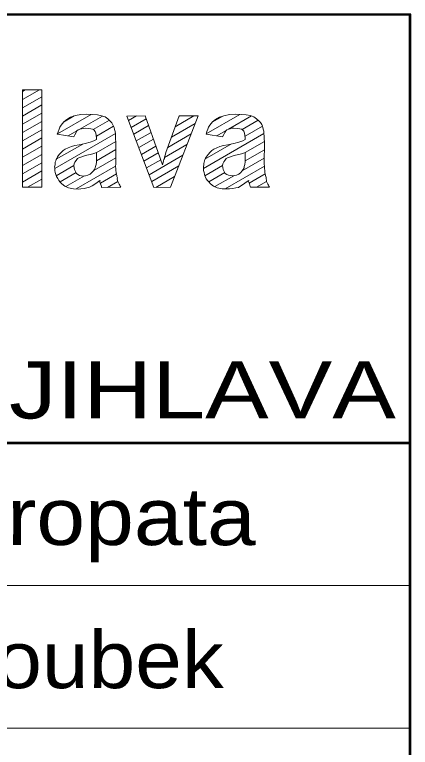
# Model space of a CAD drawing. Extents: x -670514 to -669423, y -1130798 to -1130123.
# Drawn here: x -670454.85 to -670449.3, y -1130661.82 to -1130651.55 of the extents above; entities that cross this region are included whole.
import ezdxf
from ezdxf.enums import TextEntityAlignment as Align

# ---------------------------------------------------------------- set-up
doc = ezdxf.new("R2010")
doc.units = 0
doc.header["$LTSCALE"] = 0.24
doc.layers.add('61', color=7, linetype='Continuous', lineweight=13)

msp = doc.modelspace()

# ---------------------------------------------------------------- linework, layer by layer
at = {"layer": '61'}
for p, q in [((-670454.738, -1130652.623), (-670454.702, -1130652.602)), ((-670454.738, -1130652.738), (-670454.502, -1130652.602)), ((-670454.738, -1130652.854), (-670454.47, -1130652.699)), ((-670454.739, -1130652.969), (-670454.47, -1130652.814)), ((-670454.739, -1130653.085), (-670454.47, -1130652.93)), ((-670454.249, -1130653.219), (-670453.778, -1130652.947)), ((-670454.165, -1130653.055), (-670454.015, -1130652.968)), ((-670453.942, -1130653.157), (-670453.616, -1130652.969)), ((-670453.746, -1130653.159), (-670453.52, -1130653.029)), ((-670453.251, -1130653.033), (-670453.138, -1130652.968)), ((-670453.215, -1130653.128), (-670453.004, -1130653.007)), ((-670452.597, -1130653.118), (-670452.336, -1130652.967)), ((-670452.544, -1130652.972), (-670452.537, -1130652.968)), ((-670452.163, -1130653.219), (-670451.691, -1130652.947)), ((-670452.08, -1130653.056), (-670451.93, -1130652.969)), ((-670451.851, -1130653.155), (-670451.528, -1130652.968)), ((-670451.659, -1130653.159), (-670451.432, -1130653.029)), ((-670454.739, -1130653.2), (-670454.47, -1130653.045)), ((-670453.703, -1130653.25), (-670453.462, -1130653.111)), ((-670453.179, -1130653.223), (-670452.97, -1130653.103)), ((-670452.65, -1130653.264), (-670452.317, -1130653.072)), ((-670451.618, -1130653.251), (-670451.374, -1130653.111)), ((-670454.739, -1130653.316), (-670454.47, -1130653.161)), ((-670454.286, -1130653.702), (-670453.437, -1130653.212)), ((-670454.099, -1130653.248), (-670453.976, -1130653.176)), ((-670453.143, -1130653.318), (-670452.936, -1130653.198)), ((-670452.703, -1130653.41), (-670452.375, -1130653.22)), ((-670452.201, -1130653.703), (-670451.352, -1130653.213)), ((-670452.012, -1130653.247), (-670451.89, -1130653.177)), ((-670454.739, -1130653.432), (-670454.47, -1130653.276)), ((-670453.706, -1130653.483), (-670453.432, -1130653.325)), ((-670453.107, -1130653.412), (-670452.902, -1130653.294)), ((-670451.616, -1130653.481), (-670451.346, -1130653.325)), ((-670454.739, -1130653.547), (-670454.47, -1130653.392)), ((-670454.266, -1130653.575), (-670453.895, -1130653.361)), ((-670453.702, -1130653.596), (-670453.432, -1130653.44)), ((-670453.071, -1130653.507), (-670452.868, -1130653.39)), ((-670452.747, -1130653.551), (-670452.433, -1130653.369)), ((-670452.18, -1130653.575), (-670451.806, -1130653.36)), ((-670451.616, -1130653.596), (-670451.347, -1130653.441)), ((-670454.74, -1130653.663), (-670454.47, -1130653.507)), ((-670453.035, -1130653.602), (-670452.834, -1130653.486)), ((-670452.963, -1130653.791), (-670452.49, -1130653.518)), ((-670454.74, -1130653.778), (-670454.47, -1130653.623)), ((-670453.74, -1130653.733), (-670453.432, -1130653.555)), ((-670452.999, -1130653.697), (-670452.8, -1130653.582)), ((-670451.657, -1130653.735), (-670451.348, -1130653.557)), ((-670454.74, -1130653.894), (-670454.47, -1130653.738)), ((-670454.266, -1130653.806), (-670454.018, -1130653.663)), ((-670453.985, -1130653.99), (-670453.433, -1130653.671)), ((-670452.927, -1130653.886), (-670452.548, -1130653.667)), ((-670452.181, -1130653.807), (-670451.933, -1130653.664)), ((-670451.897, -1130653.99), (-670451.347, -1130653.672)), ((-670454.668, -1130653.968), (-670454.47, -1130653.853)), ((-670454.213, -1130653.891), (-670453.988, -1130653.761)), ((-670454.129, -1130653.958), (-670453.87, -1130653.808)), ((-670453.647, -1130653.91), (-670453.421, -1130653.78)), ((-670452.871, -1130653.969), (-670452.606, -1130653.816)), ((-670452.126, -1130653.891), (-670451.903, -1130653.762)), ((-670452.043, -1130653.958), (-670451.777, -1130653.805)), ((-670451.56, -1130653.911), (-670451.336, -1130653.781)), ((-670453.548, -1130653.969), (-670453.401, -1130653.884)), ((-670451.457, -1130653.967), (-670451.315, -1130653.885)), ((-670452.668, -1130653.967), (-670452.664, -1130653.965)), ((-670469.303, -1130659.551), (-670449.299, -1130659.548)), ((-670469.297, -1130661.55), (-670449.301, -1130661.549))]:
    msp.add_line(p, q, dxfattribs=at)
at = {"layer": '61', "lineweight": 53}
msp.add_line((-670469.3, -1130657.551), (-670449.303, -1130657.548), dxfattribs=at)
msp.add_lwpolyline([(-670509.297, -1130671.564), (-670449.3, -1130671.545), (-670449.301, -1130651.548), (-670509.3, -1130651.56)], close=True, dxfattribs=at)
at = {"layer": '61'}
for points in [[(-670454.74, -1130653.968), (-670454.738, -1130652.602), (-670454.47, -1130652.602), (-670454.47, -1130653.968)], [(-670452.896, -1130653.969), (-670453.275, -1130652.969), (-670453.018, -1130652.968), (-670452.837, -1130653.479), (-670452.775, -1130653.651), (-670452.765, -1130653.622), (-670452.762, -1130653.597), (-670452.759, -1130653.577), (-670452.748, -1130653.566), (-670452.746, -1130653.544), (-670452.743, -1130653.529), (-670452.734, -1130653.504), (-670452.728, -1130653.48), (-670452.543, -1130652.968), (-670452.276, -1130652.967), (-670452.665, -1130653.967)], [(-670453.884, -1130653.532), (-670453.92, -1130653.545), (-670453.949, -1130653.556), (-670453.969, -1130653.566), (-670453.986, -1130653.591), (-670454.003, -1130653.614), (-670454.016, -1130653.638), (-670454.018, -1130653.663), (-670454.015, -1130653.693), (-670454.011, -1130653.72), (-670453.997, -1130653.744), (-670453.982, -1130653.774), (-670453.962, -1130653.789), (-670453.938, -1130653.801), (-670453.913, -1130653.806), (-670453.884, -1130653.811), (-670453.855, -1130653.805), (-670453.822, -1130653.797), (-670453.791, -1130653.785), (-670453.765, -1130653.762), (-670453.746, -1130653.74), (-670453.729, -1130653.72), (-670453.718, -1130653.694), (-670453.713, -1130653.675), (-670453.709, -1130653.664), (-670453.705, -1130653.65), (-670453.706, -1130653.638), (-670453.701, -1130653.623), (-670453.702, -1130653.601), (-670453.701, -1130653.587), (-670453.702, -1130653.562), (-670453.701, -1130653.542), (-670453.701, -1130653.481), (-670453.726, -1130653.489), (-670453.754, -1130653.5), (-670453.79, -1130653.508), (-670453.836, -1130653.516)], [(-670451.929, -1130653.691), (-670451.925, -1130653.72), (-670451.912, -1130653.744), (-670451.897, -1130653.774), (-670451.875, -1130653.787), (-670451.852, -1130653.799), (-670451.827, -1130653.804), (-670451.799, -1130653.808), (-670451.77, -1130653.804), (-670451.738, -1130653.796), (-670451.706, -1130653.785), (-670451.678, -1130653.761), (-670451.661, -1130653.74), (-670451.643, -1130653.72), (-670451.632, -1130653.696), (-670451.628, -1130653.675), (-670451.623, -1130653.662), (-670451.619, -1130653.65), (-670451.62, -1130653.637), (-670451.617, -1130653.621), (-670451.616, -1130653.601), (-670451.615, -1130653.585), (-670451.617, -1130653.56), (-670451.616, -1130653.54), (-670451.616, -1130653.48), (-670451.64, -1130653.487), (-670451.668, -1130653.498), (-670451.706, -1130653.508), (-670451.75, -1130653.516), (-670451.799, -1130653.533), (-670451.835, -1130653.544), (-670451.863, -1130653.556), (-670451.883, -1130653.565), (-670451.901, -1130653.591), (-670451.917, -1130653.613), (-670451.929, -1130653.639), (-670451.933, -1130653.663)]]:
    msp.add_lwpolyline(points, close=True, dxfattribs=at)
for points in [[(-670454.019, -1130653.26), (-670454.251, -1130653.224), (-670454.238, -1130653.188), (-670454.226, -1130653.154), (-670454.215, -1130653.127), (-670454.198, -1130653.098), (-670454.178, -1130653.075), (-670454.161, -1130653.049), (-670454.137, -1130653.032), (-670454.116, -1130653.018), (-670454.065, -1130652.983), (-670453.998, -1130652.963), (-670453.921, -1130652.948), (-670453.836, -1130652.944), (-670453.757, -1130652.948), (-670453.689, -1130652.952), (-670453.629, -1130652.964), (-670453.581, -1130652.981), (-670453.543, -1130653.008), (-670453.512, -1130653.037), (-670453.487, -1130653.062), (-670453.47, -1130653.091), (-670453.462, -1130653.11), (-670453.452, -1130653.13), (-670453.448, -1130653.156), (-670453.441, -1130653.184), (-670453.437, -1130653.216), (-670453.436, -1130653.252), (-670453.434, -1130653.289), (-670453.432, -1130653.333), (-670453.432, -1130653.639), (-670453.433, -1130653.676), (-670453.43, -1130653.704), (-670453.429, -1130653.732), (-670453.425, -1130653.761), (-670453.421, -1130653.782), (-670453.417, -1130653.801), (-670453.414, -1130653.817), (-670453.408, -1130653.834), (-670453.409, -1130653.85), (-670453.405, -1130653.87), (-670453.4, -1130653.886), (-670453.392, -1130653.906), (-670453.384, -1130653.923), (-670453.376, -1130653.939), (-670453.369, -1130653.951), (-670453.359, -1130653.968), (-670453.629, -1130653.969), (-670453.631, -1130653.956), (-670453.636, -1130653.941), (-670453.643, -1130653.918), (-670453.654, -1130653.894), (-670453.653, -1130653.886), (-670453.653, -1130653.879), (-670453.652, -1130653.875), (-670453.653, -1130653.871), (-670453.69, -1130653.899), (-670453.725, -1130653.923), (-670453.763, -1130653.948), (-670453.799, -1130653.968), (-670453.835, -1130653.977), (-670453.876, -1130653.983), (-670453.921, -1130653.988), (-670453.958, -1130653.992), (-670454.026, -1130653.988), (-670454.092, -1130653.976), (-670454.144, -1130653.951), (-670454.189, -1130653.919), (-670454.21, -1130653.895), (-670454.229, -1130653.871), (-670454.245, -1130653.845), (-670454.262, -1130653.818), (-670454.27, -1130653.79), (-670454.28, -1130653.761), (-670454.287, -1130653.733), (-670454.286, -1130653.699), (-670454.288, -1130653.68), (-670454.283, -1130653.655), (-670454.283, -1130653.635), (-670454.279, -1130653.615), (-670454.271, -1130653.598), (-670454.268, -1130653.578), (-670454.259, -1130653.562), (-670454.249, -1130653.54), (-670454.223, -1130653.508), (-670454.194, -1130653.475), (-670454.169, -1130653.451), (-670454.14, -1130653.432), (-670454.099, -1130653.416), (-670454.054, -1130653.394), (-670454.006, -1130653.383), (-670453.945, -1130653.371), (-670453.862, -1130653.354), (-670453.792, -1130653.334), (-670453.739, -1130653.316), (-670453.702, -1130653.297), (-670453.702, -1130653.274), (-670453.704, -1130653.24), (-670453.711, -1130653.207), (-670453.722, -1130653.185), (-670453.737, -1130653.164)], [(-670454.019, -1130653.26), (-670454.251, -1130653.224), (-670454.238, -1130653.188), (-670454.226, -1130653.154), (-670454.215, -1130653.127), (-670454.198, -1130653.098), (-670454.178, -1130653.075), (-670454.161, -1130653.049), (-670454.137, -1130653.032), (-670454.116, -1130653.018), (-670454.065, -1130652.983), (-670453.998, -1130652.963), (-670453.921, -1130652.948), (-670453.836, -1130652.944), (-670453.757, -1130652.948), (-670453.689, -1130652.952), (-670453.629, -1130652.964), (-670453.581, -1130652.981), (-670453.543, -1130653.008), (-670453.512, -1130653.037), (-670453.487, -1130653.062), (-670453.47, -1130653.091), (-670453.462, -1130653.11), (-670453.452, -1130653.13), (-670453.448, -1130653.156), (-670453.441, -1130653.184), (-670453.437, -1130653.216), (-670453.436, -1130653.252), (-670453.434, -1130653.289), (-670453.432, -1130653.333), (-670453.432, -1130653.639), (-670453.433, -1130653.676), (-670453.43, -1130653.704), (-670453.429, -1130653.732), (-670453.425, -1130653.761), (-670453.421, -1130653.782), (-670453.417, -1130653.801), (-670453.414, -1130653.817), (-670453.408, -1130653.834), (-670453.409, -1130653.85), (-670453.405, -1130653.87), (-670453.4, -1130653.886), (-670453.392, -1130653.906), (-670453.384, -1130653.923), (-670453.376, -1130653.939), (-670453.369, -1130653.951), (-670453.359, -1130653.968), (-670453.629, -1130653.969), (-670453.631, -1130653.956), (-670453.636, -1130653.941), (-670453.643, -1130653.918), (-670453.654, -1130653.894), (-670453.653, -1130653.886), (-670453.653, -1130653.879), (-670453.652, -1130653.875), (-670453.653, -1130653.871), (-670453.69, -1130653.899), (-670453.725, -1130653.923), (-670453.763, -1130653.948), (-670453.799, -1130653.968), (-670453.835, -1130653.977), (-670453.876, -1130653.983), (-670453.921, -1130653.988), (-670453.958, -1130653.992), (-670454.026, -1130653.988), (-670454.092, -1130653.976), (-670454.144, -1130653.951), (-670454.189, -1130653.919), (-670454.21, -1130653.895), (-670454.229, -1130653.871), (-670454.245, -1130653.845), (-670454.262, -1130653.818), (-670454.27, -1130653.79), (-670454.28, -1130653.761), (-670454.287, -1130653.733), (-670454.286, -1130653.699), (-670454.288, -1130653.68), (-670454.283, -1130653.655), (-670454.283, -1130653.635), (-670454.279, -1130653.615), (-670454.271, -1130653.598), (-670454.268, -1130653.578), (-670454.259, -1130653.562), (-670454.249, -1130653.54), (-670454.223, -1130653.508), (-670454.194, -1130653.475), (-670454.169, -1130653.451), (-670454.14, -1130653.432), (-670454.099, -1130653.416), (-670454.054, -1130653.394), (-670454.006, -1130653.383), (-670453.945, -1130653.371), (-670453.862, -1130653.354), (-670453.792, -1130653.334), (-670453.739, -1130653.316), (-670453.702, -1130653.297), (-670453.702, -1130653.274), (-670453.704, -1130653.24), (-670453.711, -1130653.207), (-670453.722, -1130653.185), (-670453.737, -1130653.164)], [(-670451.934, -1130653.26), (-670452.164, -1130653.223), (-670452.152, -1130653.186), (-670452.139, -1130653.155), (-670452.129, -1130653.127), (-670452.111, -1130653.097), (-670452.091, -1130653.073), (-670452.075, -1130653.048), (-670452.05, -1130653.033), (-670452.032, -1130653.017), (-670451.978, -1130652.984), (-670451.913, -1130652.964), (-670451.836, -1130652.946), (-670451.751, -1130652.943), (-670451.672, -1130652.948), (-670451.604, -1130652.95), (-670451.542, -1130652.963), (-670451.496, -1130652.979), (-670451.457, -1130653.007), (-670451.424, -1130653.036), (-670451.401, -1130653.061), (-670451.384, -1130653.088), (-670451.375, -1130653.109), (-670451.368, -1130653.13), (-670451.363, -1130653.154), (-670451.356, -1130653.181), (-670451.352, -1130653.215), (-670451.35, -1130653.251), (-670451.348, -1130653.287), (-670451.346, -1130653.332), (-670451.349, -1130653.638), (-670451.347, -1130653.675), (-670451.344, -1130653.703), (-670451.342, -1130653.731), (-670451.341, -1130653.76), (-670451.336, -1130653.78), (-670451.332, -1130653.802), (-670451.326, -1130653.816), (-670451.323, -1130653.832), (-670451.322, -1130653.849), (-670451.319, -1130653.869), (-670451.315, -1130653.885), (-670451.306, -1130653.906), (-670451.299, -1130653.922), (-670451.29, -1130653.938), (-670451.282, -1130653.95), (-670451.275, -1130653.966), (-670451.543, -1130653.967), (-670451.547, -1130653.956), (-670451.551, -1130653.939), (-670451.557, -1130653.919), (-670451.566, -1130653.895), (-670451.567, -1130653.887), (-670451.566, -1130653.879), (-670451.565, -1130653.874), (-670451.566, -1130653.87), (-670451.603, -1130653.897), (-670451.641, -1130653.923), (-670451.678, -1130653.946), (-670451.711, -1130653.969), (-670451.747, -1130653.976), (-670451.79, -1130653.984), (-670451.835, -1130653.987), (-670451.87, -1130653.991), (-670451.94, -1130653.988), (-670452.007, -1130653.975), (-670452.059, -1130653.951), (-670452.104, -1130653.917), (-670452.124, -1130653.893), (-670452.145, -1130653.87), (-670452.161, -1130653.847), (-670452.178, -1130653.818), (-670452.185, -1130653.788), (-670452.193, -1130653.761), (-670452.2, -1130653.73), (-670452.201, -1130653.699), (-670452.2, -1130653.678), (-670452.198, -1130653.653), (-670452.197, -1130653.635), (-670452.193, -1130653.614), (-670452.186, -1130653.598), (-670452.18, -1130653.576), (-670452.174, -1130653.56), (-670452.163, -1130653.543), (-670452.137, -1130653.508), (-670452.107, -1130653.476), (-670452.084, -1130653.451), (-670452.054, -1130653.431), (-670452.014, -1130653.415), (-670451.969, -1130653.394), (-670451.92, -1130653.381), (-670451.86, -1130653.371), (-670451.774, -1130653.353), (-670451.706, -1130653.333), (-670451.651, -1130653.317), (-670451.616, -1130653.296), (-670451.615, -1130653.272), (-670451.62, -1130653.24), (-670451.624, -1130653.208), (-670451.635, -1130653.183), (-670451.652, -1130653.163)], [(-670451.934, -1130653.26), (-670452.164, -1130653.223), (-670452.152, -1130653.186), (-670452.139, -1130653.155), (-670452.129, -1130653.127), (-670452.111, -1130653.097), (-670452.091, -1130653.073), (-670452.075, -1130653.048), (-670452.05, -1130653.033), (-670452.032, -1130653.017), (-670451.978, -1130652.984), (-670451.913, -1130652.964), (-670451.836, -1130652.946), (-670451.751, -1130652.943), (-670451.672, -1130652.948), (-670451.604, -1130652.95), (-670451.542, -1130652.963), (-670451.496, -1130652.979), (-670451.457, -1130653.007), (-670451.424, -1130653.036), (-670451.401, -1130653.061), (-670451.384, -1130653.088), (-670451.375, -1130653.109), (-670451.368, -1130653.13), (-670451.363, -1130653.154), (-670451.356, -1130653.181), (-670451.352, -1130653.215), (-670451.35, -1130653.251), (-670451.348, -1130653.287), (-670451.346, -1130653.332), (-670451.349, -1130653.638), (-670451.347, -1130653.675), (-670451.344, -1130653.703), (-670451.342, -1130653.731), (-670451.341, -1130653.76), (-670451.336, -1130653.78), (-670451.332, -1130653.802), (-670451.326, -1130653.816), (-670451.323, -1130653.832), (-670451.322, -1130653.849), (-670451.319, -1130653.869), (-670451.315, -1130653.885), (-670451.306, -1130653.906), (-670451.299, -1130653.922), (-670451.29, -1130653.938), (-670451.282, -1130653.95), (-670451.275, -1130653.966), (-670451.543, -1130653.967), (-670451.547, -1130653.956), (-670451.551, -1130653.939), (-670451.557, -1130653.919), (-670451.566, -1130653.895), (-670451.567, -1130653.887), (-670451.566, -1130653.879), (-670451.565, -1130653.874), (-670451.566, -1130653.87), (-670451.603, -1130653.897), (-670451.641, -1130653.923), (-670451.678, -1130653.946), (-670451.711, -1130653.969), (-670451.747, -1130653.976), (-670451.79, -1130653.984), (-670451.835, -1130653.987), (-670451.87, -1130653.991), (-670451.94, -1130653.988), (-670452.007, -1130653.975), (-670452.059, -1130653.951), (-670452.104, -1130653.917), (-670452.124, -1130653.893), (-670452.145, -1130653.87), (-670452.161, -1130653.847), (-670452.178, -1130653.818), (-670452.185, -1130653.788), (-670452.193, -1130653.761), (-670452.2, -1130653.73), (-670452.201, -1130653.699), (-670452.2, -1130653.678), (-670452.198, -1130653.653), (-670452.197, -1130653.635), (-670452.193, -1130653.614), (-670452.186, -1130653.598), (-670452.18, -1130653.576), (-670452.174, -1130653.56), (-670452.163, -1130653.543), (-670452.137, -1130653.508), (-670452.107, -1130653.476), (-670452.084, -1130653.451), (-670452.054, -1130653.431), (-670452.014, -1130653.415), (-670451.969, -1130653.394), (-670451.92, -1130653.381), (-670451.86, -1130653.371), (-670451.774, -1130653.353), (-670451.706, -1130653.333), (-670451.651, -1130653.317), (-670451.616, -1130653.296), (-670451.615, -1130653.272), (-670451.62, -1130653.24), (-670451.624, -1130653.208), (-670451.635, -1130653.183), (-670451.652, -1130653.163)], [(-670453.737, -1130653.164), (-670453.755, -1130653.155), (-670453.779, -1130653.146), (-670453.816, -1130653.142), (-670453.86, -1130653.138), (-670453.888, -1130653.142), (-670453.912, -1130653.147), (-670453.937, -1130653.155), (-670453.957, -1130653.163), (-670453.975, -1130653.175), (-670453.986, -1130653.2), (-670454.003, -1130653.23), (-670454.019, -1130653.26)], [(-670453.737, -1130653.164), (-670453.755, -1130653.155), (-670453.779, -1130653.146), (-670453.816, -1130653.142), (-670453.86, -1130653.138), (-670453.888, -1130653.142), (-670453.912, -1130653.147), (-670453.937, -1130653.155), (-670453.957, -1130653.163), (-670453.975, -1130653.175), (-670453.986, -1130653.2), (-670454.003, -1130653.23), (-670454.019, -1130653.26)], [(-670451.652, -1130653.163), (-670451.668, -1130653.154), (-670451.693, -1130653.146), (-670451.729, -1130653.143), (-670451.774, -1130653.138), (-670451.802, -1130653.141), (-670451.827, -1130653.147), (-670451.852, -1130653.155), (-670451.872, -1130653.164), (-670451.889, -1130653.174), (-670451.899, -1130653.198), (-670451.916, -1130653.227), (-670451.934, -1130653.26)], [(-670451.652, -1130653.163), (-670451.668, -1130653.154), (-670451.693, -1130653.146), (-670451.729, -1130653.143), (-670451.774, -1130653.138), (-670451.802, -1130653.141), (-670451.827, -1130653.147), (-670451.852, -1130653.155), (-670451.872, -1130653.164), (-670451.889, -1130653.174), (-670451.899, -1130653.198), (-670451.916, -1130653.227), (-670451.934, -1130653.26)]]:
    msp.add_lwpolyline(points, dxfattribs=at)

# ---------------------------------------------------------------- texts
for s, rotation, width, p in [('586 01 JIHLAVA ', 0.013, 1.25, (-670454.2606, -1130657.2078)), ('ing Kuropata', 359.935, 1.15, (-670454.9555, -1130658.9793))]:
    msp.add_text(s, height=0.8, rotation=rotation, dxfattribs=dict(at, width=width)).set_placement(p, align=Align.CENTER)
at = {"layer": '61', "width": 1.1}
msp.add_text('Ing. Koubek', height=0.8, rotation=0.015, dxfattribs=at).set_placement((-670458.196, -1130660.988))

doc.saveas('drawing.dxf')
